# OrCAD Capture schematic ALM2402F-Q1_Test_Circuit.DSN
size A; title: ALM2402F-Q1 Automotive, Dual Operational Amplifier With; rev: 1.3; note: Datasheet: SBOS927B  EVM: N/A
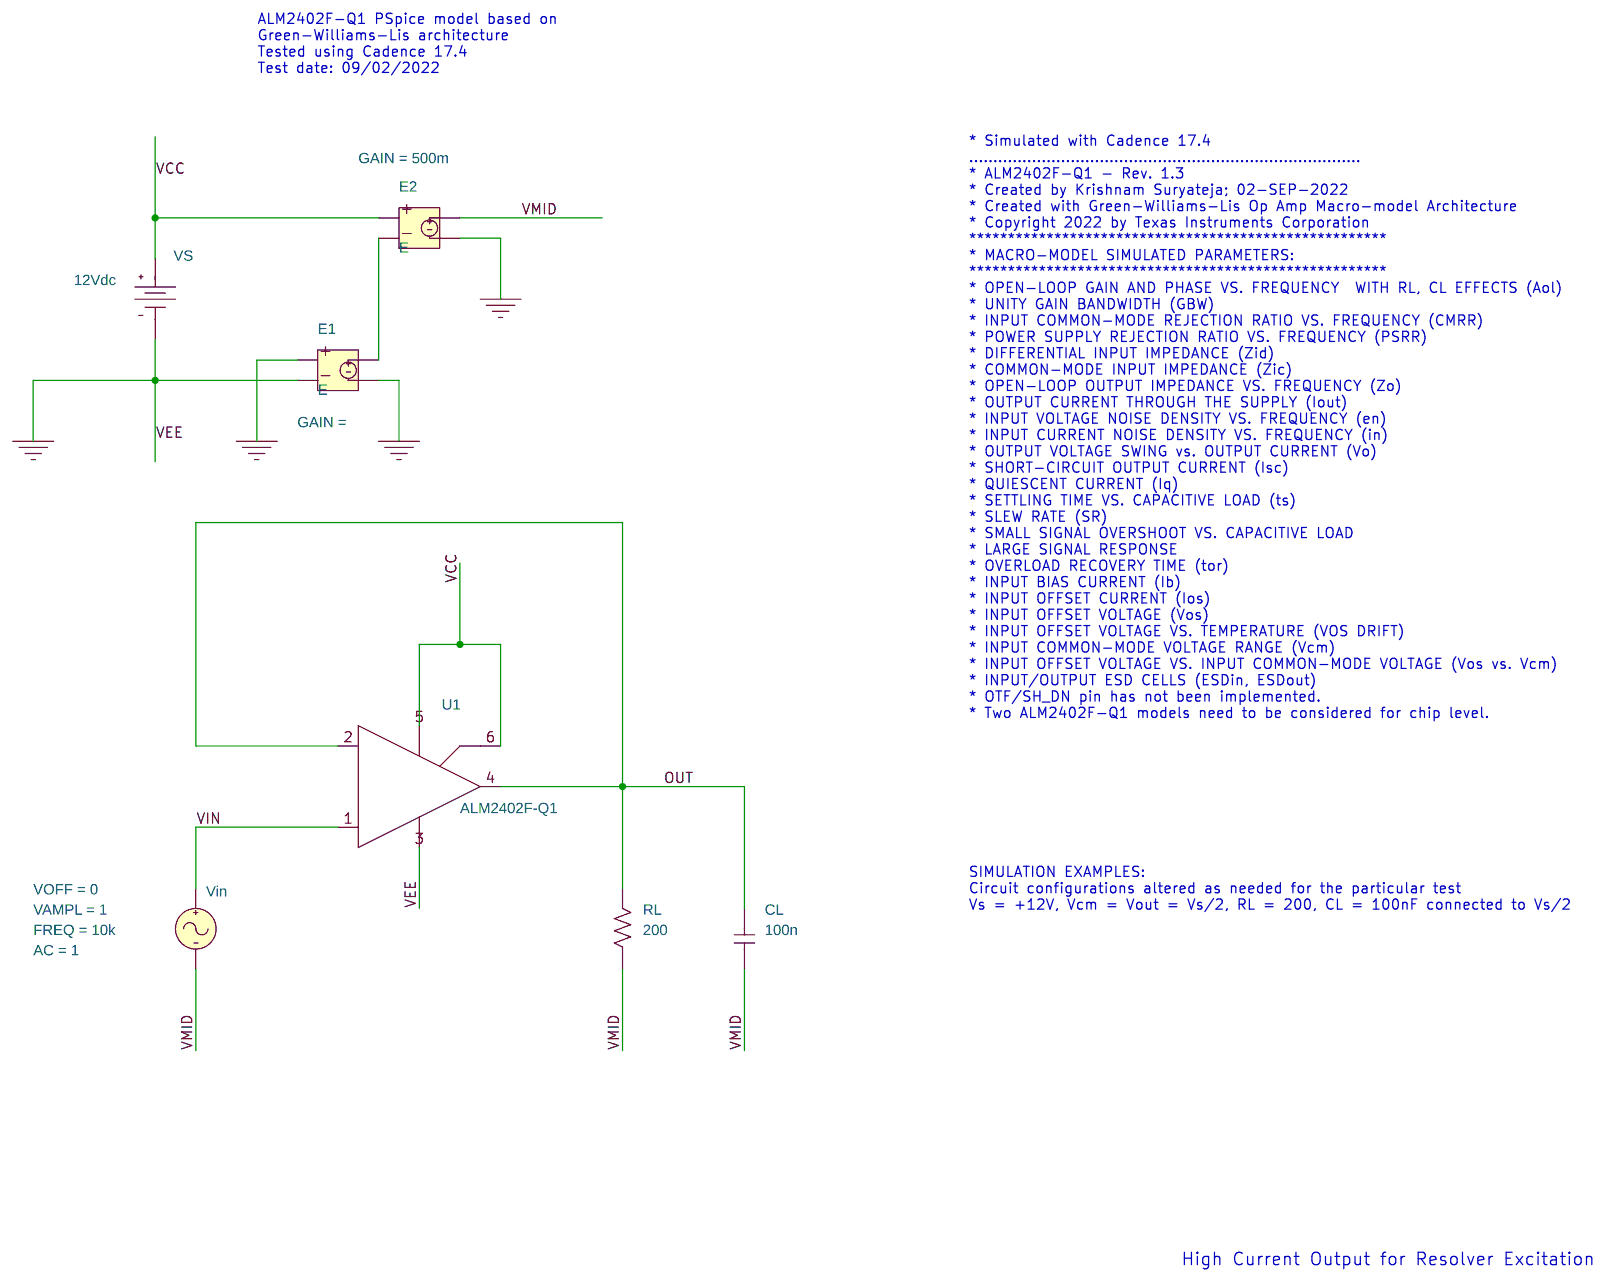
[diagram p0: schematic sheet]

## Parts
CL  100n  [RAD/CK05]
E1  E
E2  E
RL  200  [AX/RC05]
U1  ALM2402F-Q1
Vin  VSIN
VS  VDC

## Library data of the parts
CL = C
E1 = E
E2 = E: GAIN: 500m
RL = R
U1 = ALM2402F-Q1
Vin = VSIN: AC: 1; FREQ: 10k; VAMPL: 1; VOFF: 0
VS = VDC: DC: 12Vdc

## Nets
VCC: E2.1 U1.5(VS) U1.6(VS_O) VS.0(+)
VIN: U1.1(+) Vin.1(+)
0: E1.1 E1.2 E1.4 E2.4 U1.3(GND) VS.1(-)
OUT: CL.2 RL.2 U1.2(-) U1.4(OUT)
VMID: CL.1 E2.3 RL.1 Vin.2(-)
N35743: E1.3 E2.2

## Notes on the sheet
- ALM2402F-Q1 PSpice model based on
  Green-Williams-Lis architecture
  Tested using Cadence 17.4
  Test date: 09/02/2022
- * Simulated with Cadence 17.4
  .................................................................................
  * ALM2402F-Q1 - Rev. 1.3
  * Created by Krishnam Suryateja; 02-SEP-2022
  * Created with Green-Williams-Lis Op Amp Macro-model Architecture
  * Copyright 2022 by Texas Instruments Corporation
  ******************************************************
  * MACRO-MODEL SIMULATED PARAMETERS:
  ******************************************************
  * OPEN-LOOP GAIN AND PHASE VS. FREQUENCY  WITH RL, CL EFFECTS (Aol)
  * UNITY GAIN BANDWIDTH (GBW)
  * INPUT COMMON-MODE REJECTION RATIO VS. FREQUENCY (CMRR)
  * POWER SUPPLY REJECTION RATIO VS. FREQUENCY (PSRR)
  * DIFFERENTIAL INPUT IMPEDANCE (Zid)
  * COMMON-MODE INPUT IMPEDANCE (Zic)
  * OPEN-LOOP OUTPUT IMPEDANCE VS. FREQUENCY (Zo)
  * OUTPUT CURRENT THROUGH THE SUPPLY (Iout)
  * INPUT VOLTAGE NOISE DENSITY VS. FREQUENCY (en)
  * INPUT CURRENT NOISE DENSITY VS. FREQUENCY (in)
  * OUTPUT VOLTAGE SWING vs. OUTPUT CURRENT (Vo)
  * SHORT-CIRCUIT OUTPUT CURRENT (Isc)
  * QUIESCENT CURRENT (Iq)
  * SETTLING TIME VS. CAPACITIVE LOAD (ts)
  * SLEW RATE (SR)
  * SMALL SIGNAL OVERSHOOT VS. CAPACITIVE LOAD
  * LARGE SIGNAL RESPONSE
  * OVERLOAD RECOVERY TIME (tor)
  * INPUT BIAS CURRENT (Ib)
  * INPUT OFFSET CURRENT (Ios)
  * INPUT OFFSET VOLTAGE (Vos)
  * INPUT OFFSET VOLTAGE VS. TEMPERATURE (VOS DRIFT)
  * INPUT COMMON-MODE VOLTAGE RANGE (Vcm)
  * INPUT OFFSET VOLTAGE VS. INPUT COMMON-MODE VOLTAGE (Vos vs. Vcm)
  * INPUT/OUTPUT ESD CELLS (ESDin, ESDout)
  * OTF/SH_DN pin has not been implemented.
  * Two ALM2402F-Q1 models need to be considered for chip level.
- SIMULATION EXAMPLES:
  Circuit configurations altered as needed for the particular test
  Vs = +12V, Vcm = Vout = Vs/2, RL = 200, CL = 100nF connected to Vs/2
- High Current Output for Resolver Excitation
